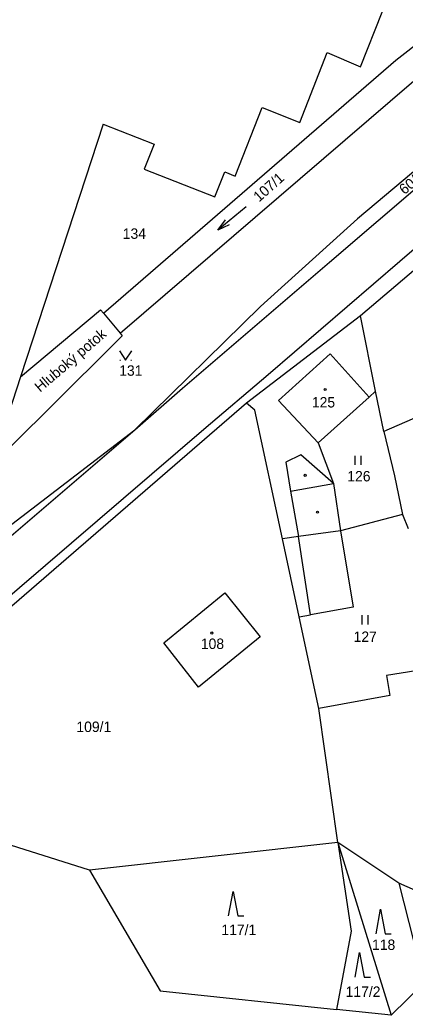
# Model space of a CAD drawing. Extents: x -670359 to -668019, y -978807 to -976674.
# Drawn here: x -670062 to -669999.1, y -977283.8 to -977121.4 of the extents above; entities that cross this region are included whole.
import ezdxf

# ---------------------------------------------------------------- set-up
doc = ezdxf.new("R2010")
doc.units = 0
for name, color, linetype in [('Hranice kat_území', 7, 'Continuous'), ('Hranice parcel', 7, 'Continuous'), ('Parcelní čísla', 7, 'Continuous'), ('Pop  PČ popisy', 7, 'Continuous'), ('Vnitřní kresba', 7, 'Continuous'), ('Značky budov', 7, 'Continuous'), ('Značky kultur', 7, 'Continuous')]:
    doc.layers.add(name, color=color, linetype=linetype)

msp = doc.modelspace()

# ---------------------------------------------------------------- linework, layer by layer
at = {"layer": 'Hranice kat_území'}
for points in [[(-670006.38, -977129.04), (-669999.35, -977111.15)], [(-670016.32, -977138.09), (-670011.86, -977126.69)], [(-670011.86, -977126.69), (-670006.38, -977129.04)], [(-670026.89, -977146.84), (-670022.48, -977135.64)], [(-670022.48, -977135.64), (-670016.32, -977138.09)], [(-670048.41, -977138.39), (-670061.94, -977179.61)], [(-670048.41, -977138.39), (-670040.1, -977141.65)], [(-670040.1, -977141.65), (-670041.7, -977145.7)], [(-670041.7, -977145.7), (-670030.18, -977150.23)], [(-670030.18, -977150.23), (-670028.56, -977146.18)], [(-670028.56, -977146.18), (-670026.89, -977146.84)], [(-670061.94, -977179.61), (-670066.67, -977194.02)]]:
    msp.add_lwpolyline(points, dxfattribs=at)
at = {"layer": 'Hranice parcel'}
for points in [[(-670000.63, -977127.93), (-669995.94, -977124.31)], [(-670035.46, -977181.47), (-670011.48, -977160.92), (-669972.1, -977127.22)], [(-669974.03, -977126.23), (-670006.9, -977153.84)], [(-670048.39, -977169.23), (-670000.63, -977127.93)], [(-670104.59, -977250.52), (-670079.48, -977228.88), (-670031.98, -977188.17), (-670021.47, -977179.22), (-669995.68, -977157.04), (-669989.1, -977151.37), (-669968.95, -977134.02), (-669965.11, -977130.8)], [(-670045.65, -977172.49), (-669997.72, -977131.3)], [(-670006.9, -977153.84), (-670022.74, -977168.15)], [(-669993.77, -977158.95), (-670006.42, -977169.66)], [(-670061.94, -977179.61), (-670048.84, -977168.7)], [(-670048.84, -977168.7), (-670048.39, -977169.23)], [(-670022.74, -977168.15), (-670043.26, -977188.26)], [(-670006.42, -977169.66), (-670025, -977183.9)], [(-670003.93, -977181.96), (-670006.42, -977169.66)], [(-670045.65, -977172.49), (-670045.31, -977172.9)], [(-670045.31, -977172.9), (-670057.51, -977185.02)], [(-669982.85, -977179.94), (-670002.6, -977188.53)], [(-670043.26, -977188.26), (-670035.46, -977181.47)], [(-670003.93, -977181.96), (-670004.99, -977182.91)], [(-670002.6, -977188.53), (-670003.93, -977181.96)], [(-670025, -977183.9), (-670096.49, -977245.64)], [(-670023.65, -977185.06), (-670025, -977183.9)], [(-670004.99, -977182.91), (-670013.34, -977190.39)], [(-670057.51, -977185.02), (-670066.67, -977194.02)], [(-670019.16, -977206.03), (-670023.65, -977185.06)], [(-670111.14, -977246.5), (-670103.49, -977239.81), (-670043.26, -977188.26)], [(-670065.71, -977205.46), (-670043.26, -977188.26)], [(-670002.6, -977188.53), (-670000.84, -977195.75)], [(-670013.34, -977190.39), (-670010.83, -977197.01)], [(-670010.83, -977197.01), (-670009.67, -977204.76)], [(-670000.84, -977195.75), (-669999.53, -977202.06)], [(-669999.53, -977202.06), (-670009.67, -977204.76)], [(-669999.53, -977202.06), (-669998.63, -977204.37)], [(-670009.67, -977204.76), (-670016.54, -977205.68)], [(-670016.54, -977205.68), (-670019.16, -977206.03)], [(-670016.43, -977218.79), (-670019.16, -977206.03)], [(-670038.5, -977223), (-670028.57, -977214.86)], [(-670028.57, -977214.86), (-670022.77, -977222.02)], [(-670013.23, -977233.75), (-670016.43, -977218.79)], [(-670032.88, -977230.23), (-670038.5, -977223)], [(-670022.77, -977222.02), (-670032.88, -977230.23)], [(-669994.99, -977227.2), (-670002.18, -977228.33)], [(-670002.18, -977228.33), (-670001.61, -977231.6)], [(-670001.61, -977231.6), (-670013.23, -977233.75)], [(-670010.11, -977255.58), (-670013.23, -977233.75)], [(-670050.66, -977260.11), (-670096.49, -977245.64)], [(-670010.11, -977255.58), (-670050.66, -977260.11)], [(-670000.16, -977262.24), (-670010.11, -977255.58)], [(-670010.11, -977255.58), (-670001.38, -977283.75)], [(-670010.11, -977255.58), (-670007.92, -977270.07)], [(-670050.66, -977260.11), (-670039.14, -977279.77)], [(-669985.76, -977268.51), (-670000.16, -977262.24)], [(-670000.16, -977262.24), (-669996.01, -977278.51)], [(-670007.92, -977270.07), (-670010.33, -977282.81)], [(-670039.14, -977279.77), (-670010.33, -977282.81)], [(-669996.01, -977278.51), (-670001.38, -977283.75)], [(-670001.38, -977283.75), (-670010.33, -977282.81)]]:
    msp.add_lwpolyline(points, dxfattribs=at)
at = {"layer": 'Vnitřní kresba'}
for points in [[(-670048.39, -977169.23), (-670045.65, -977172.49)], [(-670011.34, -977175.84), (-670019.78, -977183.48)], [(-670004.99, -977182.91), (-670011.34, -977175.84)], [(-670019.78, -977183.48), (-670013.34, -977190.39)], [(-670016.13, -977192.33), (-670018.61, -977193.54)], [(-670018.61, -977193.54), (-670017.86, -977198.25)], [(-670010.83, -977197.01), (-670016.13, -977192.33)], [(-670017.86, -977198.25), (-670010.83, -977197.01)], [(-670017.86, -977198.25), (-670016.54, -977205.68)], [(-670009.67, -977204.76), (-670007.6, -977217.21)], [(-670014.55, -977218.45), (-670016.54, -977205.68)], [(-670007.6, -977217.21), (-670014.55, -977218.45)], [(-670016.43, -977218.79), (-670014.55, -977218.45)]]:
    msp.add_lwpolyline(points, dxfattribs=at)
at = {"layer": 'Značky budov'}
for centre in [(-670012.18, -977181.68), (-670030.68, -977221.41)]:
    msp.add_circle(centre, 0.175, dxfattribs=at)
at = {"layer": 'Značky kultur'}
for p, q in [((-670025.05, -977151.85), (-670029.69, -977155.67)), ((-670045.71, -977176.87), (-670045.61, -977176.87)), ((-670043.91, -977176.87), (-670043.81, -977176.87)), ((-670007.31, -977192.47), (-670007.31, -977193.97)), ((-670006.31, -977193.97), (-670006.31, -977192.47)), ((-670006.16, -977218.5), (-670006.16, -977220)), ((-670005.16, -977220), (-670005.16, -977218.5))]:
    msp.add_line(p, q, dxfattribs=at)
for points in [[(-670027.82, -977154.78), (-670029.69, -977155.67), (-670028.46, -977154.01)], [(-670045.76, -977175.37), (-670044.76, -977176.87), (-670043.76, -977175.37)], [(-670027.95, -977267.57), (-670027.2, -977263.57), (-670026.45, -977267.57), (-670025.45, -977267.57)], [(-670003.87, -977270.49), (-670003.12, -977266.49), (-670002.37, -977270.49), (-670001.37, -977270.49)], [(-670007.29, -977277.54), (-670006.54, -977273.54), (-670005.79, -977277.54), (-670004.79, -977277.54)]]:
    msp.add_lwpolyline(points, dxfattribs=at)
for centre in [(-670012.18, -977181.68), (-670015.43, -977195.67), (-670013.43, -977201.68), (-670030.68, -977221.41)]:
    msp.add_circle(centre, 0.175, dxfattribs=at)

# ---------------------------------------------------------------- texts
at = {"layer": 'Parcelní čísla'}
for s, rotation, p in [('107/1', 41.6336, (-670022.97, -977151.17)), ('60/13', 38.9704, (-669999.24, -977149.96))]:
    msp.add_text(s, height=1.7, rotation=rotation, dxfattribs=at).set_placement(p)
for s, p in [('134', (-670045.22, -977157.09)), ('131', (-670045.8, -977179.43)), ('125', (-670014.34, -977184.61)), ('126', (-670008.56, -977196.67)), ('127', (-670007.53, -977222.86)), ('108', (-670032.47, -977224.01)), ('109/1', (-670052.79, -977237.56)), ('117/1', (-670029.12, -977270.69)), ('118', (-670004.52, -977273.12)), ('117/2', (-670008.83, -977280.78))]:
    msp.add_text(s, height=1.7, dxfattribs=at).set_placement(p)
at = {"layer": 'Pop  PČ popisy'}
msp.add_text('Hluboký potok', height=1.7, rotation=40.3172, dxfattribs=at).set_placement((-670058.72, -977182.2))

doc.saveas('drawing.dxf')
